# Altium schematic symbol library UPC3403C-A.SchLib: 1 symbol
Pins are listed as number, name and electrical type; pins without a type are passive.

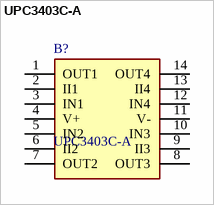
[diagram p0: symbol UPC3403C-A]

## UPC3403C-A
designator B?
Support is limited to customers who have already adopted these products.; Manufacturer_Name: Renesas Electronics; Geometry.Height: 4.5mm
footprint DIP762W60P254L1922H450Q14N
pins: 1 OUT1, 2 II1, 3 IN1, 4 V+, 5 IN2, 6 II2, 7 OUT2, 8 OUT3, 9 II3, 10 IN3, 11 V-, 12 IN4, 13 II4, 14 OUT4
